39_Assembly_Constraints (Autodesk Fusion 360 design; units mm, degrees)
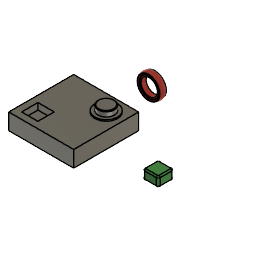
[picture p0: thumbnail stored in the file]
part number: 2026-07-20-09-23-31-459
part number: 2026-07-20-09-24-46-200
part number: 2026-07-20-09-27-21-127
part number: 2026-07-20-09-28-23-113
sketch "Sketch1" plane through (0, 0, 0) normal (0, 0, 1) x axis (1, 0, 0)
  line L1 (-50, -50) -> (50, -50)
  line L2 (-50, 50) -> (-50, -50)
  line L3 (50, 50) -> (-50, 50)
  line L4 (50, -50) -> (50, 50)
  line L5 (-50, 50) -> (50, -50)
  line L6 (50, 50) -> (-50, -50)
  point P6 (0, 0)
  point P1 (0, 0)
  point P4 (-50, 50)
  point P5 (50, 50)
  point P3 (-50, -50)
  horizontal L1
  perpendicular L1 L2
  parallel L1 L3
  parallel L2 L4
  coincident L5 P6
  coincident L6 P6
  coincident P1 P6
  dimension "d1" distance P4 P5 = 100
  dimension "d2" distance P3 P4 = 100
extrude "Extrude1" new body sketch "Sketch1" profile of L1 L2 L3 L4 along normal blind 25
sketch "Sketch2" plane through (0, 0, 25) normal (0, 0, 1) x axis (-1, 0, 0)
  line L1 (50, -50) -> (-50, -50)
  line L2 (50, 50) -> (50, -50)
  line L3 (-50, 50) -> (50, 50)
  line L4 (-50, -50) -> (-50, 50)
  line L5 (15, 40) -> (40, 40)
  line L6 (15, 15) -> (15, 40)
  line L7 (40, 15) -> (15, 15)
  line L8 (40, 40) -> (40, 15)
  point P6 (40, 40)
  point P7 (15, 40)
  point P9 (40, 15)
  horizontal L5
  vertical L6
  horizontal L7
  vertical L8
  dimension "d5" distance L3 L5 = 10
  dimension "d6" distance L2 L8 = 10 (= "d5")
  dimension "d7" distance P6 P7 = 25
  dimension "d8" distance P6 P9 = 25 (= "d7")
extrude "Extrude2" cut sketch "Sketch2" profile of L5 L6 L7 L8 against normal blind 10
sketch "Sketch3" plane through (0, 0, 25) normal (0, 0, 1) x axis (-1, 0, 0)
  line L1 (40, 40) -> (15, 40)
  line L2 (40, 15) -> (40, 40)
  line L3 (15, 15) -> (40, 15)
  line L4 (15, 40) -> (15, 15)
  line L5 (50, -50) -> (-50, -50)
  line L6 (50, 50) -> (50, -50)
  line L7 (-50, 50) -> (50, 50)
  line L8 (-50, -50) -> (-50, 50)
  line L9 (-50, -50) -> (0, 0)
  circle C1 centre (-25, -25) radius 12.5
  point P1 (0, 0)
  point P10 (0, 0)
  point P6 (-50, -50)
  point P11 (-50, -50)
  point P12 (-25, -25)
  coincident P1 P10
  coincident P6 P11
  midpoint L9 P12
  dimension "d11" diameter C1 = 25
extrude "Extrude3" add sketch "Sketch3" profile of C1 along normal blind 10
sketch "Sketch4" plane through (0, 0, 25) normal (0, 0, 1) x axis (-1, 0, 0)
  line L1 (40, 40) -> (15, 40)
  line L2 (40, 15) -> (40, 40)
  line L3 (15, 15) -> (40, 15)
  line L4 (15, 40) -> (15, 15)
  line L5 (50, -50) -> (-50, -50)
  line L6 (50, 50) -> (50, -50)
  line L7 (-50, 50) -> (50, 50)
  line L8 (-50, -50) -> (-50, 50)
  circle C1 centre (-25, -25) radius 12.5
  circle C2 centre (-25, -25) radius 17.5
  concentric C1 C2
  dimension "d14" diameter C2 = 35
extrude "Extrude4" add sketch "Sketch4" profile of C1 C2 along normal blind 2
chamfer "Chamfer1" distance 1
sketch "Sketch1" plane through (0, 0, 0) normal (0, 0, 1) x axis (1, 0, 0)
  line L1 (-12, -12) -> (12, -12)
  line L2 (-12, 12) -> (-12, -12)
  line L3 (12, 12) -> (-12, 12)
  line L4 (12, -12) -> (12, 12)
  line L5 (-12, 12) -> (12, -12)
  line L6 (12, 12) -> (-12, -12)
  point P6 (0, 0)
  point P1 (0, 0)
  point P4 (-12, 12)
  point P5 (12, 12)
  point P3 (-12, -12)
  horizontal L1
  perpendicular L1 L2
  parallel L1 L3
  parallel L2 L4
  coincident L5 P6
  coincident L6 P6
  coincident P1 P6
  dimension "d18" distance P4 P5 = 24
  dimension "d19" distance P3 P4 = 24
extrude "Extrude1" new body sketch "Sketch1" profile of L1 L2 L3 L4 along normal blind 15
fillet "Fillet1" radius 3
fillet "Fillet2" radius 2
position "Position1"
sketch "Sketch1" plane through (0, 0, 0) normal (1, 0, 0) x axis (0, 1, 0)
  line L1 (11.7782, 0) -> (0, 0)
  line L2 (5, 12.5) -> (0, 12.5)
  line L3 (5, 17.5) -> (5, 12.5)
  line L4 (0, 0) -> (0, 12.5)
  line L5 (-5, 12.5) -> (0, 12.5)
  line L6 (-5, 17.5) -> (-5, 12.5)
  line L7 (4.5, 16.75) -> (5, 16.75)
  line L8 (3.4404, 12.5) -> (4.5, 16.75)
  line L9 (-3.4404, 12.5) -> (-4.5, 16.75)
  line L10 (-4.5, 16.75) -> (-5, 16.75)
  line L11 (3.9702, 12.5) -> (3.9702, 14.625)
  line L12 (-3.9702, 12.5) -> (-3.9702, 14.625)
  arc A1 centre (0, 11.255) radius 8 clockwise from (-5, 17.5) to (5, 17.5)
  point P1 (0, 0)
  point P2 (0, 0)
  point P4 (0, 12.5)
  point P7 (0, 12.5)
  point P5 (5, 12.5)
  point P8 (-5, 12.5)
  point P6 (5, 17.5)
  point P9 (-5, 17.5)
  point P11 (5, 16.75)
  point P13 (3.4404, 12.5)
  point P16 (-5, 16.75)
  point P12 (4.5, 16.75)
  point P14 (-4.5, 16.75)
  point P15 (-3.4404, 12.5)
  point P17 (3.9702, 14.625)
  point P18 (3.9702, 12.5)
  point P19 (-3.9702, 14.625)
  point P20 (-3.9702, 12.5)
  coincident P1 P2
  horizontal L1
  parallel L1 L2
  perpendicular L2 L3
  vertical P1 P4
  symmetric P4 L4 P7
  symmetric P5 L4 P8
  symmetric P6 L4 P9
  coincident L3 P11
  perpendicular L3 L7
  coincident L2 P13
  symmetric L4 P11 P16
  symmetric L4 P12 P14
  symmetric L4 P13 P15
  midpoint L8 P17
  coincident L2 P18
  perpendicular L2 L11
  symmetric L4 P17 P19
  symmetric L4 P18 P20
  dimension "d26" = 25
  dimension "d27" distance P4 P5 = 5
  dimension "d28" distance P5 P6 = 5
  dimension "d29" radius A1 = 8
  dimension "d31" distance P6 L7 = 0.75
  dimension "d32" distance P11 P12 = 0.5
  dimension "d33" angle L3 L8 = 14
  dimension "d34" distance P18 P20 = 7.9404
revolve "Revolve1" sketch "Sketch1" AlongAngle 360
fillet "Fillet1" radius 3.75
position "Position2"
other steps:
create_component "CreateComponent1"
create_component "CreateComponent2"
create_component "CreateComponent3"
